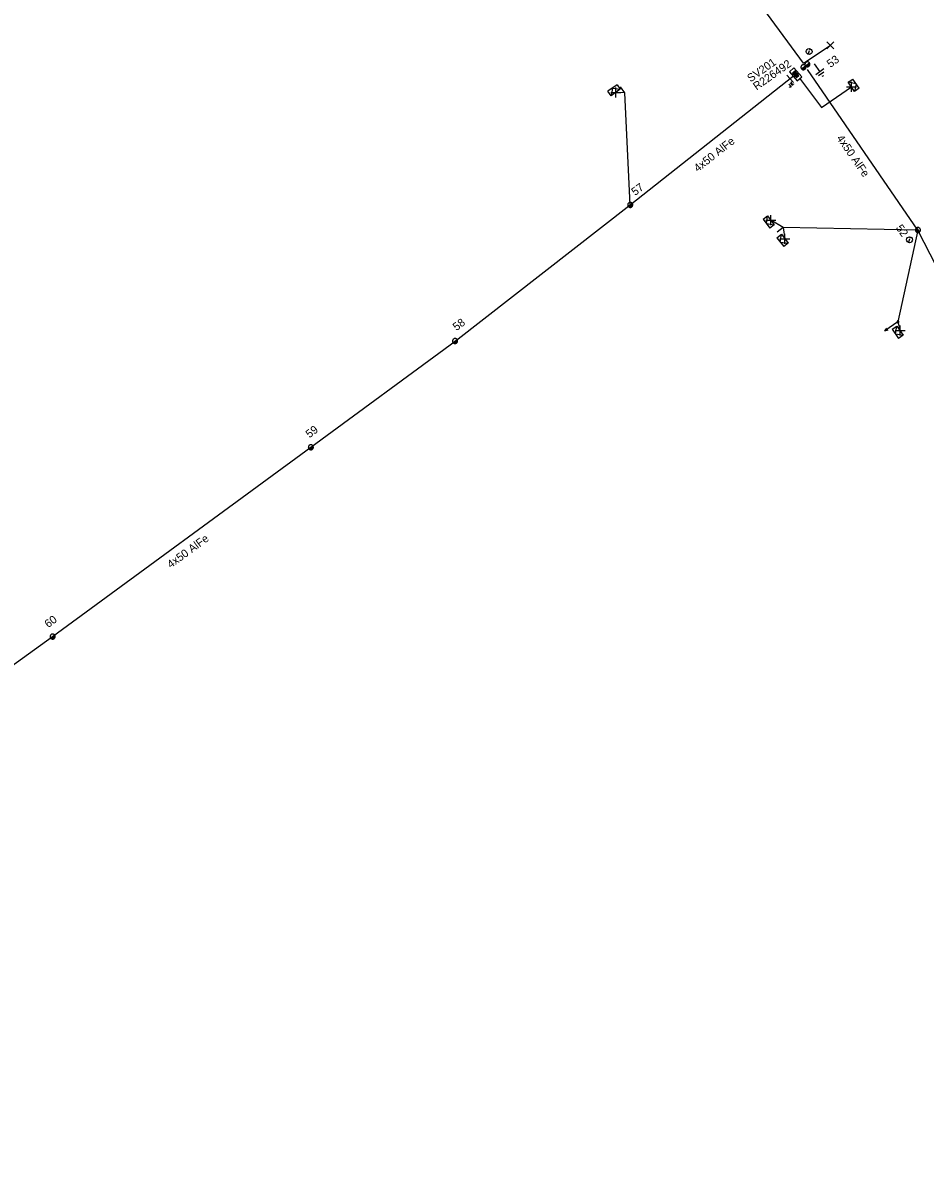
# Model space of a CAD drawing. Extents: x -544780 to -541582, y -1198995 to -1196551.
# Drawn here: x -542832.9 to -542720.2, y -1198149.8 to -1198008.2 of the extents above; entities that cross this region are included whole.
import ezdxf

# ---------------------------------------------------------------- set-up
doc = ezdxf.new("R2010")
doc.units = 0
for name, color, linetype in [('Vrstva 1', 7, 'Continuous'), ('Vrstva 10', 7, 'Continuous'), ('Vrstva 13', 7, 'Continuous'), ('Vrstva 14', 7, 'Continuous'), ('Vrstva 15', 7, 'Continuous'), ('Vrstva 18', 7, 'Continuous'), ('Vrstva 2', 7, 'Continuous'), ('Vrstva 28', 7, 'Continuous'), ('Vrstva 29', 7, 'Continuous'), ('Vrstva 30', 7, 'Continuous'), ('Vrstva 31', 7, 'Continuous'), ('Vrstva 34', 7, 'Continuous'), ('Vrstva 36', 7, 'Continuous'), ('Vrstva 52', 7, 'Continuous'), ('Vrstva 54', 7, 'Continuous'), ('Vrstva 59', 7, 'Continuous'), ('Vrstva 8', 7, 'Continuous'), ('Vrstva 9', 7, 'Continuous')]:
    doc.layers.add(name, color=color, linetype=linetype)

# ---------------------------------------------------------------- blocks, each defined once
blk = doc.blocks.new('NN440')
at = {"layer": 'Vrstva 2'}
for points in [[(0.63, 0), (0.63, 0.06), (0.62, 0.13), (0.6, 0.19), (0.58, 0.25), (0.55, 0.31), (0.51, 0.37), (0.47, 0.42), (0.42, 0.46), (0.37, 0.51), (0.32, 0.54), (0.26, 0.57), (0.2, 0.59), (0.13, 0.61), (0.07, 0.62), (0, 0.63), (-0.06, 0.62), (-0.13, 0.61), (-0.19, 0.59), (-0.26, 0.57), (-0.31, 0.54), (-0.37, 0.51), (-0.42, 0.46), (-0.47, 0.42), (-0.51, 0.37), (-0.54, 0.31), (-0.57, 0.25), (-0.6, 0.19), (-0.62, 0.13), (-0.63, 0.06), (-0.63, 0), (-0.63, -0.07), (-0.62, -0.14), (-0.6, -0.2), (-0.57, -0.26), (-0.54, -0.32), (-0.51, -0.37), (-0.47, -0.43), (-0.42, -0.47), (-0.37, -0.51), (-0.31, -0.55), (-0.26, -0.58), (-0.19, -0.6), (-0.13, -0.62), (-0.06, -0.63), (0, -0.63), (0.07, -0.63), (0.13, -0.62), (0.2, -0.6), (0.26, -0.58), (0.32, -0.55), (0.37, -0.51), (0.42, -0.47), (0.47, -0.43), (0.51, -0.37), (0.55, -0.32), (0.58, -0.26), (0.6, -0.2), (0.62, -0.14), (0.63, -0.07), (0.63, 0)], [(-0.63, 0), (0.63, 0)], [(-0.6, -0.18), (0.57, -0.18)], [(-0.51, -0.32), (0.5, -0.32)], [(-0.37, -0.47), (0.35, -0.47)]]:
    blk.add_lwpolyline(points, dxfattribs=at)
blk = doc.blocks.new('NN450')
at = {"layer": 'Vrstva 2'}
for points in [[(0, 0), (0, 0.07), (-0.01, 0.13), (-0.03, 0.19), (-0.05, 0.25), (-0.08, 0.31), (-0.12, 0.37), (-0.16, 0.42), (-0.21, 0.46), (-0.26, 0.51), (-0.31, 0.54), (-0.37, 0.57), (-0.43, 0.59), (-0.5, 0.61), (-0.56, 0.62), (-0.63, 0.62), (-0.69, 0.62), (-0.75, 0.61), (-0.82, 0.59), (-0.88, 0.57), (-0.94, 0.54), (-0.99, 0.51), (-1.04, 0.46), (-1.09, 0.42), (-1.13, 0.37), (-1.17, 0.31), (-1.2, 0.25), (-1.22, 0.19), (-1.24, 0.13), (-1.25, 0.07), (-1.25, 0), (-1.25, -0.07), (-1.24, -0.13), (-1.22, -0.19), (-1.2, -0.25), (-1.17, -0.31), (-1.13, -0.37), (-1.09, -0.42), (-1.04, -0.46), (-0.99, -0.51), (-0.94, -0.54), (-0.88, -0.57), (-0.82, -0.59), (-0.75, -0.61), (-0.69, -0.62), (-0.62, -0.63), (-0.56, -0.62), (-0.5, -0.61), (-0.43, -0.59), (-0.37, -0.57), (-0.31, -0.54), (-0.26, -0.51), (-0.21, -0.46), (-0.16, -0.42), (-0.12, -0.37), (-0.08, -0.31), (-0.05, -0.25), (-0.03, -0.19), (-0.01, -0.13), (0, -0.07), (0, 0)], [(1.25, 0), (1.25, 0.07), (1.24, 0.13), (1.22, 0.19), (1.2, 0.25), (1.17, 0.31), (1.13, 0.37), (1.09, 0.42), (1.04, 0.46), (0.99, 0.51), (0.94, 0.54), (0.88, 0.57), (0.82, 0.59), (0.75, 0.61), (0.69, 0.62), (0.62, 0.62), (0.56, 0.62), (0.5, 0.61), (0.43, 0.59), (0.37, 0.57), (0.31, 0.54), (0.26, 0.51), (0.21, 0.46), (0.16, 0.42), (0.12, 0.37), (0.08, 0.31), (0.05, 0.25), (0.03, 0.19), (0.01, 0.13), (0, 0.07), (0, 0), (0, -0.07), (0.01, -0.13), (0.03, -0.19), (0.05, -0.25), (0.08, -0.31), (0.12, -0.37), (0.16, -0.42), (0.21, -0.46), (0.26, -0.51), (0.31, -0.54), (0.37, -0.57), (0.43, -0.59), (0.5, -0.61), (0.56, -0.62), (0.63, -0.63), (0.69, -0.62), (0.75, -0.61), (0.82, -0.59), (0.88, -0.57), (0.94, -0.54), (0.99, -0.51), (1.04, -0.46), (1.09, -0.42), (1.13, -0.37), (1.17, -0.31), (1.2, -0.25), (1.22, -0.19), (1.24, -0.13), (1.25, -0.07), (1.25, 0)], [(-1.25, 0), (1.25, 0)], [(-1.23, -0.16), (-0.02, -0.16)], [(-1.16, -0.32), (-0.09, -0.32)], [(-1.03, -0.47), (-0.22, -0.47)], [(0.02, -0.16), (1.23, -0.16)], [(0.09, -0.32), (1.16, -0.32)], [(0.22, -0.47), (1.03, -0.47)]]:
    blk.add_lwpolyline(points, dxfattribs=at)
blk = doc.blocks.new('NN560')
at = {"layer": 'Vrstva 2'}
for points in [[(2, 0), (1.59, 0.14)], [(0, 0), (2, 0)], [(2, 0), (1.59, -0.13)]]:
    blk.add_lwpolyline(points, dxfattribs=at)
blk = doc.blocks.new('NN840')
at = {"layer": 'Vrstva 15'}
for points in [[(0, 0.62), (0, -0.63)], [(-0.75, -0.71), (-0.75, -0.66)], [(-0.73, -0.76), (-0.75, -0.71)], [(-0.66, -0.8), (-0.73, -0.76)], [(-0.63, -0.8), (-0.66, -0.8)], [(-0.56, -0.76), (-0.63, -0.8)], [(-0.54, -0.71), (-0.56, -0.76)], [(-0.54, -0.38), (-0.54, -0.71)], [(-0.33, -0.38), (-0.33, -0.8)], [(-0.33, -0.64), (-0.13, -0.38)], [(-0.26, -0.56), (-0.09, -0.8)]]:
    blk.add_lwpolyline(points, dxfattribs=at)
blk = doc.blocks.new('NN770')
at = {"layer": 'Vrstva 10'}
for p, q in [((0, 0.19), (0, 0.26)), ((0, -0.28), (0, 0.11))]:
    blk.add_line(p, q, dxfattribs=at)
blk.add_circle((0, -0.01), 0.375, dxfattribs=at)
blk = doc.blocks.new('NN800')
at = {"layer": 'Vrstva 1'}
for points in [[(-0.44, 0.44), (0.44, -0.44)], [(-0.44, -0.44), (0.44, 0.44)]]:
    blk.add_lwpolyline(points, dxfattribs=at)
blk = doc.blocks.new('NN620')
at = {"layer": 'Vrstva 8'}
for points in [[(0.75, 0), (-0.75, 0)], [(-0.75, 0), (-0.75, -0.75)], [(0.75, -0.75), (0.75, 0)], [(-0.75, -0.75), (0.75, -0.75)], [(0.37, -0.18), (-0.38, -0.18)], [(-0.38, -0.18), (-0.38, -0.56)], [(-0.38, -0.56), (0.37, -0.56)], [(0.32, -0.23), (-0.33, -0.23)], [(-0.33, -0.23), (-0.33, -0.51)], [(-0.33, -0.51), (0.32, -0.51)], [(0.27, -0.27), (-0.28, -0.27)], [(-0.28, -0.27), (-0.28, -0.46)], [(-0.28, -0.46), (0.27, -0.46)], [(0.23, -0.32), (-0.23, -0.32)], [(-0.23, -0.32), (-0.23, -0.42)], [(-0.23, -0.42), (0.23, -0.42)], [(-0.19, -0.37), (0.19, -0.37)], [(0.23, -0.42), (0.23, -0.32)], [(0.27, -0.46), (0.27, -0.27)], [(0.32, -0.51), (0.32, -0.23)], [(0.37, -0.56), (0.37, -0.18)]]:
    blk.add_lwpolyline(points, dxfattribs=at)
blk = doc.blocks.new('NN630')
at = {"layer": 'Vrstva 9'}
for points in [[(0, -0.7), (-0.7, 0)], [(-0.7, -0.7), (-0.7, 0), (0.7, 0), (0.7, -0.7)], [(-0.7, -0.7), (0.7, -0.7)], [(0, -0.7), (0.7, 0)]]:
    blk.add_lwpolyline(points, dxfattribs=at)
blk = doc.blocks.new('NN810')
at = {"layer": 'Vrstva 14'}
for points in [[(0, -0.64), (0, -1.89)], [(0.63, -1.89), (-0.62, -1.89)], [(0.39, -2.2), (-0.4, -2.2)], [(0, -2.52), (-0.12, -2.52)], [(0.14, -2.52), (0, -2.52)]]:
    blk.add_lwpolyline(points, dxfattribs=at)
blk = doc.blocks.new('NN500')
at = {"layer": 'Vrstva 2'}
for points in [[(0, -0.24), (0.02, -0.23), (0.05, -0.23), (0.07, -0.22), (0.09, -0.22), (0.12, -0.2), (0.14, -0.19), (0.16, -0.18), (0.17, -0.16), (0.19, -0.14), (0.2, -0.12), (0.21, -0.1), (0.22, -0.07), (0.23, -0.05), (0.23, -0.02), (0.23, 0), (0.23, 0.02), (0.23, 0.05), (0.22, 0.07), (0.21, 0.1), (0.2, 0.12), (0.19, 0.14), (0.17, 0.16), (0.16, 0.17), (0.14, 0.19), (0.12, 0.2), (0.09, 0.21), (0.07, 0.22), (0.05, 0.23), (0.02, 0.23), (0, 0.23), (-0.03, 0.23), (-0.05, 0.23), (-0.07, 0.22), (-0.1, 0.21), (-0.12, 0.2), (-0.14, 0.19), (-0.16, 0.17), (-0.18, 0.16), (-0.19, 0.14), (-0.2, 0.12), (-0.22, 0.1), (-0.22, 0.07), (-0.23, 0.05), (-0.23, 0.02), (-0.24, 0), (-0.23, -0.02), (-0.23, -0.05), (-0.22, -0.07), (-0.22, -0.1), (-0.2, -0.12), (-0.19, -0.14), (-0.18, -0.16), (-0.16, -0.18), (-0.14, -0.19), (-0.12, -0.2), (-0.1, -0.22), (-0.07, -0.22), (-0.05, -0.23), (-0.03, -0.23), (0, -0.24)], [(0, -0.24), (0.02, -0.23), (0.05, -0.23), (0.07, -0.22), (0.09, -0.22), (0.12, -0.2), (0.14, -0.19), (0.16, -0.18), (0.17, -0.16), (0.19, -0.14), (0.2, -0.12), (0.21, -0.1), (0.22, -0.07), (0.23, -0.05), (0.23, -0.02), (0.23, 0), (0.23, 0.02), (0.23, 0.05), (0.22, 0.07), (0.21, 0.1), (0.2, 0.12), (0.19, 0.14), (0.17, 0.16), (0.16, 0.17), (0.14, 0.19), (0.12, 0.2), (0.09, 0.21), (0.07, 0.22), (0.05, 0.23), (0.02, 0.23), (0, 0.23), (-0.03, 0.23), (-0.05, 0.23), (-0.07, 0.22), (-0.1, 0.21), (-0.12, 0.2), (-0.14, 0.19), (-0.16, 0.17), (-0.18, 0.16), (-0.19, 0.14), (-0.2, 0.12), (-0.22, 0.1), (-0.22, 0.07), (-0.23, 0.05), (-0.23, 0.02), (-0.24, 0), (-0.23, -0.02), (-0.23, -0.05), (-0.22, -0.07), (-0.22, -0.1), (-0.2, -0.12), (-0.19, -0.14), (-0.18, -0.16), (-0.16, -0.18), (-0.14, -0.19), (-0.12, -0.2), (-0.1, -0.22), (-0.07, -0.22), (-0.05, -0.23), (-0.03, -0.23), (0, -0.24)], [(0, -0.21), (0.02, -0.2), (0.04, -0.2), (0.06, -0.2), (0.08, -0.19), (0.1, -0.18), (0.12, -0.17), (0.14, -0.15), (0.15, -0.14), (0.16, -0.12), (0.18, -0.1), (0.19, -0.08), (0.19, -0.06), (0.2, -0.04), (0.2, -0.02), (0.2, 0), (0.2, 0.02), (0.2, 0.04), (0.19, 0.06), (0.19, 0.08), (0.18, 0.1), (0.16, 0.12), (0.15, 0.14), (0.14, 0.15), (0.12, 0.17), (0.1, 0.18), (0.08, 0.19), (0.06, 0.19), (0.04, 0.2), (0.02, 0.2), (0, 0.2), (-0.02, 0.2), (-0.04, 0.2), (-0.06, 0.19), (-0.08, 0.19), (-0.1, 0.18), (-0.12, 0.17), (-0.14, 0.15), (-0.15, 0.14), (-0.17, 0.12), (-0.18, 0.1), (-0.19, 0.08), (-0.2, 0.06), (-0.2, 0.04), (-0.21, 0.02), (-0.21, 0), (-0.21, -0.02), (-0.2, -0.04), (-0.2, -0.06), (-0.19, -0.08), (-0.18, -0.1), (-0.17, -0.12), (-0.15, -0.14), (-0.14, -0.15), (-0.12, -0.17), (-0.1, -0.18), (-0.08, -0.19), (-0.06, -0.2), (-0.04, -0.2), (-0.02, -0.2), (0, -0.21)], [(0, -0.18), (0.02, -0.18), (0.04, -0.17), (0.05, -0.17), (0.07, -0.16), (0.09, -0.15), (0.1, -0.14), (0.12, -0.13), (0.13, -0.12), (0.14, -0.1), (0.15, -0.09), (0.16, -0.07), (0.17, -0.05), (0.17, -0.04), (0.17, -0.02), (0.17, 0), (0.17, 0.02), (0.17, 0.04), (0.17, 0.05), (0.16, 0.07), (0.15, 0.09), (0.14, 0.1), (0.13, 0.12), (0.12, 0.13), (0.1, 0.14), (0.09, 0.15), (0.07, 0.16), (0.05, 0.17), (0.04, 0.17), (0.02, 0.17), (0, 0.18), (-0.02, 0.17), (-0.04, 0.17), (-0.06, 0.17), (-0.07, 0.16), (-0.09, 0.15), (-0.1, 0.14), (-0.12, 0.13), (-0.13, 0.12), (-0.14, 0.1), (-0.15, 0.09), (-0.16, 0.07), (-0.17, 0.05), (-0.17, 0.04), (-0.18, 0.02), (-0.18, 0), (-0.18, -0.02), (-0.17, -0.04), (-0.17, -0.05), (-0.16, -0.07), (-0.15, -0.09), (-0.14, -0.1), (-0.13, -0.12), (-0.12, -0.13), (-0.1, -0.14), (-0.09, -0.15), (-0.07, -0.16), (-0.06, -0.17), (-0.04, -0.17), (-0.02, -0.18), (0, -0.18)], [(0, -0.15), (0.01, -0.15), (0.03, -0.14), (0.04, -0.14), (0.06, -0.13), (0.07, -0.13), (0.08, -0.12), (0.1, -0.11), (0.11, -0.1), (0.12, -0.09), (0.13, -0.07), (0.13, -0.06), (0.14, -0.05), (0.14, -0.03), (0.14, -0.02), (0.14, 0), (0.14, 0.01), (0.14, 0.03), (0.14, 0.04), (0.13, 0.06), (0.13, 0.07), (0.12, 0.09), (0.11, 0.1), (0.1, 0.11), (0.08, 0.12), (0.07, 0.13), (0.06, 0.13), (0.04, 0.14), (0.03, 0.14), (0.01, 0.14), (0, 0.15), (-0.02, 0.14), (-0.03, 0.14), (-0.05, 0.14), (-0.06, 0.13), (-0.07, 0.13), (-0.09, 0.12), (-0.1, 0.11), (-0.11, 0.1), (-0.12, 0.09), (-0.13, 0.07), (-0.13, 0.06), (-0.14, 0.04), (-0.14, 0.03), (-0.15, 0.01), (-0.15, 0), (-0.15, -0.02), (-0.14, -0.03), (-0.14, -0.05), (-0.13, -0.06), (-0.13, -0.07), (-0.12, -0.09), (-0.11, -0.1), (-0.1, -0.11), (-0.09, -0.12), (-0.07, -0.13), (-0.06, -0.13), (-0.05, -0.14), (-0.03, -0.14), (-0.02, -0.15), (0, -0.15)], [(0, -0.12), (0.01, -0.12), (0.02, -0.11), (0.03, -0.11), (0.05, -0.11), (0.06, -0.1), (0.07, -0.09), (0.08, -0.09), (0.09, -0.08), (0.09, -0.07), (0.1, -0.06), (0.11, -0.05), (0.11, -0.04), (0.11, -0.02), (0.11, -0.01), (0.12, 0), (0.11, 0.01), (0.11, 0.02), (0.11, 0.04), (0.11, 0.05), (0.1, 0.06), (0.09, 0.07), (0.09, 0.08), (0.08, 0.09), (0.07, 0.09), (0.06, 0.1), (0.05, 0.11), (0.03, 0.11), (0.02, 0.11), (0.01, 0.12), (0, 0.12), (-0.01, 0.12), (-0.03, 0.11), (-0.04, 0.11), (-0.05, 0.11), (-0.06, 0.1), (-0.07, 0.09), (-0.08, 0.09), (-0.09, 0.08), (-0.1, 0.07), (-0.1, 0.06), (-0.11, 0.05), (-0.11, 0.04), (-0.12, 0.02), (-0.12, 0.01), (-0.12, 0), (-0.12, -0.01), (-0.12, -0.02), (-0.11, -0.04), (-0.11, -0.05), (-0.1, -0.06), (-0.1, -0.07), (-0.09, -0.08), (-0.08, -0.09), (-0.07, -0.09), (-0.06, -0.1), (-0.05, -0.11), (-0.04, -0.11), (-0.03, -0.11), (-0.01, -0.12), (0, -0.12)], [(0, -0.09), (0.01, -0.09), (0.02, -0.09), (0.03, -0.08), (0.03, -0.08), (0.04, -0.08), (0.05, -0.07), (0.06, -0.07), (0.06, -0.06), (0.07, -0.05), (0.07, -0.04), (0.08, -0.04), (0.08, -0.03), (0.08, -0.02), (0.09, -0.01), (0.09, 0), (0.09, 0.01), (0.08, 0.02), (0.08, 0.03), (0.08, 0.03), (0.07, 0.04), (0.07, 0.05), (0.06, 0.06), (0.06, 0.06), (0.05, 0.07), (0.04, 0.07), (0.03, 0.08), (0.03, 0.08), (0.02, 0.08), (0.01, 0.09), (0, 0.09), (-0.01, 0.09), (-0.02, 0.08), (-0.03, 0.08), (-0.04, 0.08), (-0.04, 0.07), (-0.05, 0.07), (-0.06, 0.06), (-0.07, 0.06), (-0.07, 0.05), (-0.08, 0.04), (-0.08, 0.03), (-0.08, 0.03), (-0.09, 0.02), (-0.09, 0.01), (-0.09, 0), (-0.09, -0.01), (-0.09, -0.02), (-0.08, -0.03), (-0.08, -0.04), (-0.08, -0.04), (-0.07, -0.05), (-0.07, -0.06), (-0.06, -0.07), (-0.05, -0.07), (-0.04, -0.08), (-0.04, -0.08), (-0.03, -0.08), (-0.02, -0.09), (-0.01, -0.09), (0, -0.09)], [(0, -0.06), (0, -0.06), (0.01, -0.06), (0.02, -0.05), (0.02, -0.05), (0.03, -0.05), (0.03, -0.05), (0.04, -0.04), (0.04, -0.04), (0.05, -0.03), (0.05, -0.03), (0.05, -0.02), (0.05, -0.02), (0.05, -0.01), (0.06, -0.01), (0.06, 0), (0.06, 0.01), (0.05, 0.01), (0.05, 0.02), (0.05, 0.02), (0.05, 0.03), (0.05, 0.03), (0.04, 0.04), (0.04, 0.04), (0.03, 0.05), (0.03, 0.05), (0.02, 0.05), (0.02, 0.05), (0.01, 0.06), (0, 0.06), (0, 0.06), (-0.01, 0.06), (-0.01, 0.06), (-0.02, 0.05), (-0.02, 0.05), (-0.03, 0.05), (-0.03, 0.05), (-0.04, 0.04), (-0.04, 0.04), (-0.05, 0.03), (-0.05, 0.03), (-0.05, 0.02), (-0.06, 0.02), (-0.06, 0.01), (-0.06, 0.01), (-0.06, 0), (-0.06, -0.01), (-0.06, -0.01), (-0.06, -0.02), (-0.05, -0.02), (-0.05, -0.03), (-0.05, -0.03), (-0.04, -0.04), (-0.04, -0.04), (-0.03, -0.05), (-0.03, -0.05), (-0.02, -0.05), (-0.02, -0.05), (-0.01, -0.06), (-0.01, -0.06), (0, -0.06)], [(0, -0.03), (0, -0.03), (0, -0.03), (0.01, -0.03), (0.01, -0.03), (0.01, -0.02), (0.02, -0.02), (0.02, -0.02), (0.02, -0.02), (0.02, -0.02), (0.02, -0.01), (0.02, -0.01), (0.03, -0.01), (0.03, -0.01), (0.03, 0), (0.03, 0), (0.03, 0), (0.03, 0.01), (0.03, 0.01), (0.02, 0.01), (0.02, 0.01), (0.02, 0.02), (0.02, 0.02), (0.02, 0.02), (0.02, 0.02), (0.01, 0.02), (0.01, 0.02), (0.01, 0.03), (0, 0.03), (0, 0.03), (0, 0.03), (0, 0.03), (-0.01, 0.03), (-0.01, 0.03), (-0.01, 0.02), (-0.02, 0.02), (-0.02, 0.02), (-0.02, 0.02), (-0.02, 0.02), (-0.02, 0.02), (-0.03, 0.01), (-0.03, 0.01), (-0.03, 0.01), (-0.03, 0.01), (-0.03, 0), (-0.03, 0), (-0.03, 0), (-0.03, -0.01), (-0.03, -0.01), (-0.03, -0.01), (-0.03, -0.01), (-0.02, -0.02), (-0.02, -0.02), (-0.02, -0.02), (-0.02, -0.02), (-0.02, -0.02), (-0.01, -0.03), (-0.01, -0.03), (-0.01, -0.03), (0, -0.03), (0, -0.03)], [(0.23, 0), (0.7, 0)]]:
    blk.add_lwpolyline(points, dxfattribs=at)
blk = doc.blocks.new('NN510')
at = {"layer": 'Vrstva 2'}
blk.add_lwpolyline([(0, 0), (0, 0.94)], dxfattribs=at)

msp = doc.modelspace()

# ---------------------------------------------------------------- linework, layer by layer
at = {"layer": 'Vrstva 1'}
for points in [[(-542735.37, -1198013.24), (-542755, -1197986.48)], [(-542693.01, -1198116.88), (-542700.71, -1198085.64), (-542704.72, -1198067.68), (-542708.66, -1198058.32), (-542721.08, -1198034.07), (-542734.88, -1198014.03)], [(-542924.66, -1198163.13), (-542924.66, -1198163.13), (-542909.26, -1198142.87), (-542899.34, -1198130.66), (-542877.32, -1198117.58), (-542860.26, -1198107.27), (-542829.18, -1198084.86), (-542796.92, -1198061.21), (-542778.91, -1198047.94), (-542757.02, -1198030.94), (-542736.62, -1198014.82)]]:
    msp.add_lwpolyline(points, dxfattribs=at)
at = {"layer": 'Vrstva 52'}
msp.add_lwpolyline([(-542735.88, -1198015.12), (-542733.13, -1198018.78), (-542729.39, -1198016.19)], dxfattribs=at)
at = {"layer": 'Vrstva 54'}
for points in [[(-542757.02, -1198030.94), (-542757.68, -1198016.93), (-542758.83, -1198016.9)], [(-542721.08, -1198034.07), (-542737.91, -1198033.75)], [(-542721.08, -1198034.07), (-542723.58, -1198045.53), (-542723.32, -1198046.64)]]:
    msp.add_lwpolyline(points, dxfattribs=at)
at = {"layer": 'Vrstva 59'}
for points in [[(-542735.37, -1198013.24), (-542732.03, -1198011.01)], [(-542737.91, -1198033.75), (-542739.45, -1198032.85)], [(-542737.91, -1198033.75), (-542737.72, -1198035.16)]]:
    msp.add_lwpolyline(points, dxfattribs=at)

# ---------------------------------------------------------------- block references
at = {"layer": 'Vrstva 13', "xscale": 0.5}
for name, p, yscale, rotation in [('NN450', (-542735.14, -1198013.55), 0.5, 35.81465833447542), ('NN440', (-542757.02, -1198030.93), 0.5, 36.58704171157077), ('NN440', (-542721.08, -1198034.07), 0.5, -54.590188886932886), ('NN500', (-542723.58, -1198045.53), 0.5000000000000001, -145.17300002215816), ('NN440', (-542778.91, -1198047.94), 0.5, 36.84455552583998), ('NN440', (-542796.92, -1198061.21), 0.5, 36.84455552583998), ('NN440', (-542829.18, -1198084.86), 0.5, 36.84455552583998)]:
    msp.add_blockref(name, p, dxfattribs=dict(at, yscale=yscale, rotation=rotation))
at = {"layer": 'Vrstva 13'}
for name, p, rotation in [('NN510', (-542757.68, -1198016.93), 35.82939444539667), ('NN510', (-542737.9, -1198033.75), 127.28149447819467), ('NN560', (-542723.58, -1198045.53), -145.17294458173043)]:
    msp.add_blockref(name, p, dxfattribs=dict(at, rotation=rotation))
at = {"layer": 'Vrstva 15', "rotation": 35.07440281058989}
msp.add_blockref('NN810', (-542734.43, -1198012.77), dxfattribs=at)
at = {"layer": 'Vrstva 18', "rotation": 41.59430831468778}
msp.add_blockref('NN840', (-542737.04, -1198015.19), dxfattribs=at)
at = {"layer": 'Vrstva 28', "rotation": -48.46699996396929}
msp.add_blockref('NN620', (-542736.09, -1198014.37), dxfattribs=at)
at = {"layer": 'Vrstva 31'}
for p, rotation in [((-542758.83, -1198016.9), -144.17060559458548), ((-542729.39, -1198016.19), 125.07274450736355), ((-542739.45, -1198032.85), -53.38624997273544), ((-542737.72, -1198035.16), -52.718505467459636), ((-542723.32, -1198046.64), -55.17294450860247)]:
    msp.add_blockref('NN630', p, dxfattribs=dict(at, rotation=rotation))
at = {"layer": 'Vrstva 34'}
msp.add_blockref('NN800', (-542732.03, -1198011.01), dxfattribs=at)
for p, rotation in [((-542729.39, -1198016.19), 45), ((-542758.83, -1198016.9), 45), ((-542739.45, -1198032.85), 44.99999995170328), ((-542737.72, -1198035.16), 45), ((-542723.32, -1198046.64), 45.000000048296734)]:
    msp.add_blockref('NN800', p, dxfattribs=dict(at, rotation=rotation))
at = {"layer": 'Vrstva 36'}
for p, rotation in [((-542734.67, -1198011.76), -18.70401939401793), ((-542722.13, -1198035.28), -18.70401937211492)]:
    msp.add_blockref('NN770', p, dxfattribs=dict(at, rotation=rotation))

# ---------------------------------------------------------------- texts
at = {"layer": 'Vrstva 14'}
for s, rotation, p in [('53', 35.815, (-542732.02, -1198013.84)), ('57', 36.587, (-542756.42, -1198029.83)), ('52', 305.41, (-542723.9, -1198033.82)), ('58', 36.845, (-542778.73, -1198046.71)), ('59', 36.845, (-542797.1, -1198060.1)), ('60', 36.845, (-542829.72, -1198083.82))]:
    msp.add_text(s, height=1, rotation=rotation, dxfattribs=at).set_placement(p)
at = {"layer": 'Vrstva 2'}
for rotation, p in [(38.306, (-542748.59, -1198026.88)), (304.548, (-542731.3, -1198022.6)), (36.257, (-542814.42, -1198076.37))]:
    msp.add_text('4x50 AlFe', height=1, rotation=rotation, dxfattribs=at).set_placement(p)
at = {"layer": 'Vrstva 29'}
msp.add_text('R226492', height=1, rotation=35.074, dxfattribs=at).set_placement((-542741.24, -1198016.65))
at = {"layer": 'Vrstva 30'}
msp.add_text('SV201', height=1, rotation=35.074, dxfattribs=at).set_placement((-542741.98, -1198015.64))

doc.saveas('drawing.dxf')
